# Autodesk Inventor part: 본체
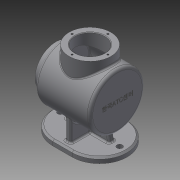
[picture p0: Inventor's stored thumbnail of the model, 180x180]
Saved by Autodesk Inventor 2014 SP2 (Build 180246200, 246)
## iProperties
Created: 2016-04
Part Number: 본체
Material: 일반
Document SubType Name: Modeling
Designer: 201-25
Density: 1 g/cm^3
Appearance: 기본값
Author: 201-25
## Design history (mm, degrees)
sketch "스케치1"
  geometry: L1 (-67.5, 50)-(67.5, 50); L2 (67.5, 50)-(67.5, -50); L3 (67.5, -50)-(-67.5, -50); L4 (-67.5, -50)-(-67.5, 50); 3 further points
  constraints: 8 end point, 2 midpoint, 2 parallel, 1 horizontal, 1 horizontal alignment, 1 perpendicular, 1 vertical alignment
  dimensions: "d5" = 135 distance of L2.end L3.end; "d6" = 100 distance of L1.end L2.end
extrude "돌출1" new body sketch "스케치1" distance "d7" = 10; taper "d8" = 0 deg
fillet "모깎기1" dims "d9" = 50
sketch "스케치2"
  geometry: L1 (50, 0)-(-50, 0) reference; C1 r 50 at (0, 79); 1 further point
  constraints: 1 centre point
  dimensions: "d10" = 100 diameter of C1; "d11" = 79 distance from line of L1 C1.centre
extrude "돌출2" join sketch "스케치2" stored distance "d12" = 100; taper "d13" = 0 deg
sketch "스케치3"
  geometry: C1 r 38 at (0, 0); 1 further point
  constraints: 1 centre point
  dimensions: "d14" = 76 diameter of C1
extrude "돌출3" join sketch "스케치3" distance "d15" = 12; taper "d16" = 0 deg
node "작업 평면1"
sketch "스케치4"
  geometry: C1 r 38 at (0, 0); 1 further point
  constraints: 1 centre point
  dimensions: "d18" = 76 diameter of C1
extrude "돌출4" join sketch "스케치4" stored distance "d19" = 12; taper "d20" = 0 deg
sketch "스케치5"
  geometry: L1 (-5, 40)-(5, 40); L2 (5, 40)-(5, -40); L3 (5, -40)-(-5, -40); L4 (-5, -40)-(-5, 40); C1 r 38 at (0, 0) reference; 2 further points
  constraints: 8 end point, 2 midpoint, 2 parallel, 1 horizontal, 1 horizontal alignment, 1 perpendicular, 1 vertical alignment
  dimensions: "d27" = 10 distance of L2.end L3.end; "d28" = 80 distance of L1.end L2.end
extrude "돌출5" join sketch "스케치5" stored distance "d29" = 12; taper "d30" = 0 deg
sketch "스케치7"
  geometry: C1 r 27 at (0, 0); 1 further point
  constraints: 1 centre point
  dimensions: "d35" = 54 diameter of C1
extrude "돌출7" cut sketch "스케치7" distance "d36" = 15; taper "d37" = 0 deg
sketch "스케치10"
  geometry: C1 r 27 at (0, 0) reference; 2 further points
  dimensions: "d38" = 32.5 distance of C1.centre point (32.5, 0)
hole "구멍1" sketch "스케치10" at (32.5, 0) diameter "d39" = 3.242; stored, may be unused: countersink angle "d43" = 90 deg, drill point angle "d45" = 118 deg; dims "d40" = 8, "d41" = 19.05, "d42" = 4.775, "d44" = 10
chamfer "모따기1" distance "d49" = 1; stored, may be unused: second distance "d50" = 2, angle "d51" = 45 deg
fillet "모깎기2" dims "d52" = 5
fillet "모깎기3" dims "d53" = 3
sketch "스케치11"
  geometry: C1 r 38 at (0, 0) reference; 1 further point
  dimensions: "d54" = 32.5 distance of point (32.5, 0) C1.centre
hole "구멍2" sketch "스케치11" at (32.5, 0) diameter "d55" = 3.242; stored, may be unused: countersink angle "d59" = 90 deg, drill point angle "d61" = 118 deg; dims "d56" = 8, "d57" = 19.05, "d58" = 4.775, "d60" = 10
chamfer "모따기2" distance "d65" = 3; stored, may be unused: second distance "d66" = 2, angle "d67" = 45 deg
fillet "모깎기4" dims "d68" = 3
fillet "모깎기5" dims "d69" = 3
sketch "스케치12"
  geometry: C1 r 47 at (0, 0); 1 further point
  constraints: 1 centre point
  dimensions: "d70" = 94 diameter of C1
extrude "돌출8" cut sketch "스케치12" distance "d71" = 94; taper "d72" = 0 deg
sketch "스케치13"
  geometry: C1 r 27 at (0, 0)
  constraints: 1 centre point
  dimensions: "d73" = 54 diameter of C1
extrude "돌출9" cut sketch "스케치13" stored distance "d74" = 90; taper "d75" = 0 deg
chamfer "모따기3" distance "d76" = 1; stored, may be unused: second distance "d77" = 2, angle "d78" = 45 deg
sketch "스케치15"
  geometry: L1 (-4.203, -29.035)-(-4.203, 29.035); L2 (-4.203, 29.035)-(4.203, 29.035); L3 (4.203, 29.035)-(4.203, -29.035); L4 (4.203, -29.035)-(-4.203, -29.035); C1 r 50 at (0, 0) reference; 3 further points
  constraints: 2 midpoint, 1 horizontal alignment, 1 vertical alignment, 2 other
feature "엠보싱1" sketch "스케치15" dims "d5" = 135, "d6" = 100, "d79" = 0.5, "d80" = 0
sketch "스케치16"
  geometry: C1 r 5 at (-54, 0); C2 r 5 at (54, 0); 1 further point
  constraints: 2 centre point
  dimensions: "d87" = 10 diameter of C1; "d88" = 10 diameter of C2; "d89" = 54 distance of point (0, 0) C1.centre; "d90" = 54 distance of point (0, 0) C2.centre
extrude "돌출10" cut sketch "스케치16" stored distance "d85" = 90; taper "d86" = 0 deg
fillet "모깎기6" dims "d91" = 2
fillet "모깎기7" dims "d92" = 5
sketch "스케치17"
  geometry: L1 (45, 29)-(-45, 29) reference; L2 (17.5, 10)-(-17.5, 10) reference; L3 (-64.5, 10)-(-17.5, 10) reference; L4 (-36.071, 32.036)-(-40, 9.756); 2 further points
  constraints: 2 end point
  dimensions: "d93" = 100 deg angle of L3 L4; "d94" = 40 horizontal distance of L4.end point (0, 0)
feature "리브1" sketch "스케치17" dims "d95" = 10, "d96" = 10, "d97" = 0, "d98" = 0, "d99" = 1, "d100" = 1
fillet "모깎기8" dims "d101" = 3
fillet "모깎기9" dims "d102" = 3
node "솔리드1"
pattern_circular "원형 패턴1" dims angle "d47" = 360 deg
pattern_circular "원형 패턴2" dims angle "d63" = 360 deg
mirror "대칭1"
other parameters: "d17" = 144
